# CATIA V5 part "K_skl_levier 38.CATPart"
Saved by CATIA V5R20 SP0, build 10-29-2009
Part number: skl_levier 38
Publications: "longueur axe pivot", "liaison 28/38 sur 38", "liaison 23/57/38 sur 38", "liaison 38/51 sur 38", "Plan.+30", "Droite.1", "Droite.2", "Droite.3", "Droite.4", "Droite.5"
Bounding box of the stored display mesh (mm): x 30 to 180, y -720 to 275, z -55 to 725
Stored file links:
  G:\Khaled_CFAO_2011\SIL\SIL_GR2\mdardier\Khaled\CAD_ThinkMOTION\K_skl_levier 38.CATPart
  G:\Khaled_CFAO_2011\SIL\SIL_GR2\mdardier\Khaled\CAD_ThinkMOTION\K_skl_ass_tandem.CATProduct
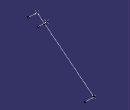
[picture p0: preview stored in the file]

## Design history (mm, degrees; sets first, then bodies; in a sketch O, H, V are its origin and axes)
External parameters (linked from other documents)
  `External.longueur axe pivot` = 150 mm
Set1
  Point1 "liaison 28/38 sur 38": linked copy from another document
  Point2 "liaison 23/57/38 sur 38": linked copy from another document
  Point3 "liaison 38/51 sur 38": linked copy from another document
  Plane1 "Plan.+30": linked copy from another document
Set2
  Line1: type PtPt, FirstPoint Point1, SecondPoint Point2
  Line2: type Angle, LineFirstUpto Line1, RefPoint Point3, Start 0, End 0, Angle 90
  Line3: type Normal, RefPoint Point1, RefSkin Plane1, Start 0, End 150 {= `External.longueur axe pivot`}
  Line4: type Normal, RefPoint Point3, RefSkin Plane1, Start 0, End 150 {= `External.longueur axe pivot`}
  Line5: type Normal, RefPoint Point2, RefSkin Plane1, Start 0, End 150 {= `External.longueur axe pivot`}
Body1 (main body)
